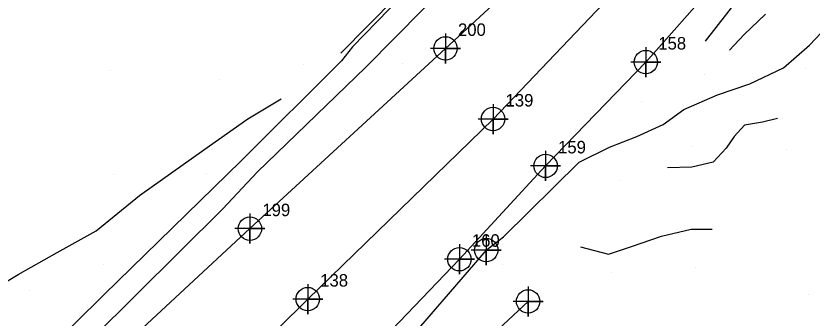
# Model space of a CAD drawing. Extents: x 1497074 to 1501343, y 481943 to 486114.
# Drawn here: x 1498449.4 to 1498608.9, y 484735.3 to 484795.7 of the extents above; entities that cross this region are included whole.
import ezdxf

# ---------------------------------------------------------------- set-up
doc = ezdxf.new("R2010")
doc.units = 0
for name, color, linetype in [('Exist DTM Breakline', 7, 'Continuous'), ('Exist DTM Breakline Cogo Point CELL', 7, 'Continuous'), ('Exist DTM Crownline', 7, 'Continuous'), ('Exist DTM Crownline Cogo Number', 7, 'Continuous'), ('Exist DTM Crownline Cogo Point CELL', 7, 'Continuous'), ('Exist Roads EOP', 7, 'Continuous'), ('Exist Roads EOP Cogo Number', 7, 'Continuous'), ('Exist Roads EOP Cogo Point CELL', 7, 'Continuous'), ('PH Exist DTM Breakline', 7, 'Continuous'), ('PH Exist DTM Point', 7, 'Continuous')]:
    doc.layers.add(name, color=color, linetype=linetype)

msp = doc.modelspace()

# ---------------------------------------------------------------- linework, layer by layer
at = {"layer": 'Exist DTM Breakline'}
for points in [[(1498543.58, 484748.87), (1498525.36, 484727.77), (1498504.08, 484707.5), (1498489.17, 484691.7), (1498485.31, 484688.34), (1498482.58, 484685.28), (1498481.93, 484681.96), (1498482.73, 484679.64), (1498478.75, 484676.92), (1498480.53, 484675.33), (1498483.37, 484674.39), (1498490.41, 484673.6), (1498498.06, 484675.92), (1498501.69, 484676.67)], [(1498505.9, 484699.42), (1498512.03, 484705.74), (1498521.32, 484710.01), (1498551.97, 484738.6)]]:
    msp.add_lwpolyline(points, dxfattribs=at)
at = {"layer": 'Exist DTM Breakline Cogo Point CELL'}
for points in [[(1498543.58, 484751.87), (1498543.58, 484745.87), (1498543.58, 484748.87), (1498546.58, 484748.87), (1498540.58, 484748.87)], [(1498551.97, 484741.6), (1498551.97, 484735.6), (1498551.97, 484738.6), (1498554.97, 484738.6), (1498548.97, 484738.6)]]:
    msp.add_lwpolyline(points, dxfattribs=at)
for centre in [(1498543.58, 484748.87), (1498551.97, 484738.6)]:
    msp.add_circle(centre, 2.34, dxfattribs=at)
at = {"layer": 'Exist DTM Crownline'}
msp.add_lwpolyline([(1498174.51, 484418.76), (1498211.76, 484454.63), (1498248.88, 484490.3), (1498287.28, 484525.89), (1498324.11, 484560.63), (1498360.29, 484595.61), (1498397.16, 484630.83), (1498419.58, 484652.79), (1498435.06, 484667.86), (1498471.56, 484703.24), (1498507.82, 484739.07), (1498544.95, 484775.1), (1498579.44, 484811.19), (1498593.31, 484825.81), (1498614.8, 484848.72), (1498648.9, 484888.1), (1498682.16, 484928.34), (1498714.31, 484969.37), (1498734.43, 484994.62)], dxfattribs=at)
at = {"layer": 'Exist DTM Crownline Cogo Point CELL'}
for points in [[(1498544.95, 484778.1), (1498544.95, 484772.1), (1498544.95, 484775.1), (1498547.95, 484775.1), (1498541.95, 484775.1)], [(1498507.82, 484742.07), (1498507.82, 484736.07), (1498507.82, 484739.07), (1498510.82, 484739.07), (1498504.82, 484739.07)]]:
    msp.add_lwpolyline(points, dxfattribs=at)
for centre in [(1498544.95, 484775.1), (1498507.82, 484739.07)]:
    msp.add_circle(centre, 2.34, dxfattribs=at)
at = {"layer": 'Exist Roads EOP'}
for points in [[(1498743.66, 484987.16), (1498738.5, 484978.99), (1498725.1, 484961.13), (1498703.01, 484933.77), (1498691.76, 484919.76), (1498658.67, 484879.67), (1498641.02, 484858.8), (1498630.75, 484847.82), (1498623.1, 484838.96), (1498603.65, 484817.74), (1498589.5, 484802.3), (1498575.55, 484786.5), (1498555.48, 484765.72), (1498538.21, 484747.04), (1498518.63, 484726.67), (1498501.9, 484709.28), (1498485.08, 484691.46), (1498474.43, 484677.64), (1498470.63, 484672.31)], [(1498165.98, 484428.62), (1498180, 484442.69), (1498201.86, 484464.11), (1498239.3, 484499.9), (1498276.43, 484536.47), (1498313.13, 484573.18), (1498338.89, 484599.2), (1498349.09, 484609.46), (1498368.89, 484629.31), (1498383.9, 484644.63), (1498405.77, 484666.89), (1498429.88, 484691.21), (1498457.88, 484717.62), (1498496.23, 484753.16), (1498535.42, 484789.23), (1498556.84, 484809.01), (1498564.6, 484818.66), (1498566.38, 484823.54), (1498565.95, 484832.29), (1498567.61, 484834.53), (1498567.66, 484834.73)]]:
    msp.add_lwpolyline(points, dxfattribs=at)
at = {"layer": 'Exist Roads EOP Cogo Point CELL'}
for points in [[(1498535.42, 484792.23), (1498535.42, 484786.23), (1498535.42, 484789.23), (1498538.42, 484789.23), (1498532.42, 484789.23)], [(1498575.55, 484789.5), (1498575.55, 484783.5), (1498575.55, 484786.5), (1498578.55, 484786.5), (1498572.55, 484786.5)], [(1498555.48, 484768.72), (1498555.48, 484762.72), (1498555.48, 484765.72), (1498558.48, 484765.72), (1498552.48, 484765.72)], [(1498496.23, 484756.16), (1498496.23, 484750.16), (1498496.23, 484753.16), (1498499.23, 484753.16), (1498493.23, 484753.16)], [(1498538.21, 484750.04), (1498538.21, 484744.04), (1498538.21, 484747.04), (1498541.21, 484747.04), (1498535.21, 484747.04)]]:
    msp.add_lwpolyline(points, dxfattribs=at)
for centre in [(1498535.42, 484789.23), (1498575.55, 484786.5), (1498555.48, 484765.72), (1498496.23, 484753.16), (1498538.21, 484747.04)]:
    msp.add_circle(centre, 2.34, dxfattribs=at)
at = {"layer": 'PH Exist DTM Breakline'}
msp.add_line((1498514.47, 484788.26), (1498528.02, 484802.02), dxfattribs=at)
for points in [[(1498359.22, 484628.11), (1498384.86, 484653.26), (1498405.36, 484673.77), (1498430.29, 484697.78), (1498443.63, 484710.75), (1498464.77, 484731.29), (1498490.84, 484757.11), (1498497.71, 484764.47), (1498519.45, 484785.49), (1498553.87, 484820.26), (1498564.01, 484831.41), (1498565.79, 484832.49)], [(1498516.8, 484789.57), (1498551.16, 484824.86)], [(1498587.48, 484790.67), (1498598.66, 484805.04), (1498604.04, 484813.23), (1498607.95, 484817.39), (1498611.76, 484821.39), (1498615.32, 484824.33)], [(1498543.58, 484748.87), (1498547.05, 484751.53), (1498562.17, 484766.44), (1498568.25, 484769.48), (1498573.77, 484771.58), (1498579.01, 484774.03), (1498583.19, 484777.03), (1498589.92, 484779.92), (1498596.37, 484782.13), (1498603.17, 484785.32), (1498608.38, 484789.9), (1498613.04, 484794.82), (1498618.97, 484801.06)], [(1498599.54, 484796.11), (1498595.29, 484792.03), (1498592.32, 484788.9)], [(1498516.8, 484789.57), (1498514.61, 484786.75), (1498494.45, 484766.74), (1498466.99, 484739.94), (1498443.94, 484717.22), (1498412.06, 484686), (1498372.6, 484647.73), (1498355.93, 484631.24)], [(1498442.44, 484739.6), (1498449.8, 484743.97), (1498457.64, 484748.4), (1498465.41, 484752.75), (1498474.14, 484759.78), (1498487.03, 484768.95), (1498495.81, 484775.13), (1498502.49, 484779.15)], [(1498601.94, 484775.22), (1498598.92, 484774.45), (1498595.34, 484773.9), (1498593.27, 484771.58), (1498591.68, 484769.28), (1498589.02, 484766.49), (1498584.78, 484765.44), (1498579.88, 484765.32)], [(1498562.49, 484749.53), (1498568.11, 484748.06), (1498572.67, 484749.58), (1498578.68, 484751.69), (1498584.63, 484753.06), (1498588.84, 484753.09)]]:
    msp.add_lwpolyline(points, dxfattribs=at)
at = {"layer": 'PH Exist DTM Point'}
for p, q in [((1498526.81, 484786.11), (1498526.81, 484786.11)), ((1498468.23, 484784.77), (1498468.23, 484784.77)), ((1498507, 484785.93), (1498507, 484785.93)), ((1498607.59, 484785.26), (1498607.59, 484785.26)), ((1498490.09, 484783), (1498490.09, 484783)), ((1498587.33, 484783.91), (1498587.33, 484783.91)), ((1498574.75, 484778.57), (1498574.75, 484778.57)), ((1498584.63, 484769.56), (1498584.63, 484769.56)), ((1498603.78, 484768.99), (1498603.78, 484768.99)), ((1498469, 484764.03), (1498469, 484764.03)), ((1498487.51, 484764.12), (1498487.51, 484764.12)), ((1498570.26, 484762.83), (1498570.26, 484762.83)), ((1498466.89, 484746.03), (1498466.89, 484746.03)), ((1498546.86, 484746.06), (1498546.86, 484746.06)), ((1498585.56, 484745.48), (1498585.56, 484745.48)), ((1498568.71, 484744.29), (1498568.71, 484744.29)), ((1498452.06, 484740.75), (1498452.06, 484740.75)), ((1498608.14, 484740.06), (1498608.14, 484740.06))]:
    msp.add_line(p, q, dxfattribs=at)

# ---------------------------------------------------------------- texts
at = {"layer": 'Exist DTM Crownline Cogo Number'}
for s, p in [('139', (1498547.45, 484777.6)), ('138', (1498510.32, 484741.57))]:
    msp.add_text(s, height=2.5, dxfattribs=at).set_placement(p)
at = {"layer": 'Exist Roads EOP Cogo Number'}
for s, p in [('200', (1498537.92, 484791.73)), ('158', (1498578.05, 484789)), ('159', (1498557.98, 484768.22)), ('199', (1498498.73, 484755.66)), ('160', (1498540.71, 484749.54))]:
    msp.add_text(s, height=2.5, dxfattribs=at).set_placement(p)

doc.saveas('drawing.dxf')
